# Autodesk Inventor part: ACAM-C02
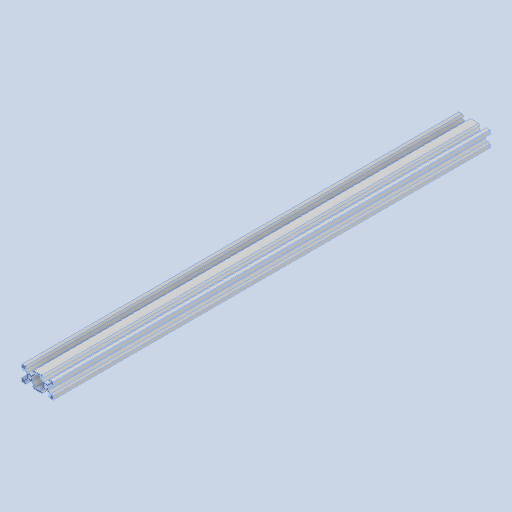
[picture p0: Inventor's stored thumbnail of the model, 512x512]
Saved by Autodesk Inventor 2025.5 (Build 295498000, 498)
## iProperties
Created: 2019-07
Part Number: ACAM-C02
Material: SOLIDWORKS Materials|6063-T5
Document SubType Name: Modeling
Designer: Luis M
Density: 2.7 g/cm^3
Appearance: blue anodized aluminum
Description: Perfil V-Slot 2040 × 550
Sending System: SolidWorks 2018
Last Author: Danish
Last Saved: 2020-09-29
Material_BOM: Aluminio
Proceso_BOM: Comercial
Author: Luis M
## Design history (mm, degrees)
fillet "Fillet1"
sketch "Boceto1"
  geometry: L1 (-15.1, 4.9)-(-15.1, 0.5) reference; L2 (-14.6, 0)-(-10.2, 0) reference; L3 (-10.2, 0)-(-8.2, 2) reference; L4 (-8.2, 2)-(-10.6, 2) reference; L5 (-10.6, 2)-(-10.6, 3.439) reference; L6 (-10.6, 3.439)-(-7.639, 6.4) reference; L7 (-7.639, 6.4)-(-2.561, 6.4) reference; L8 (-2.561, 6.4)-(0.4, 3.439) reference; L9 (0.4, 3.439)-(0.4, 2) reference; L10 (0.4, 2)-(-2, 2) reference; L11 (-2, 2)-(0, 0) reference; L12 (0, 0)-(10.214, 0) reference; L13 (10.214, 0)-(12.214, 2) reference; L14 (12.214, 2)-(9.4, 2) reference; L15 (9.4, 2)-(9.4, 3.439) reference; L16 (9.4, 3.439)-(12.361, 6.4) reference; L17 (12.361, 6.4)-(17.439, 6.4) reference; L18 (17.439, 6.4)-(20.4, 3.439) reference; L19 (20.4, 3.439)-(20.4, 2) reference; L20 (20.4, 2)-(18.414, 2) reference; L21 (18.414, 2)-(20, 0) reference; L22 (20, 0)-(24.4, 0) reference; L23 (24.9, 0.5)-(24.9, 4.9) reference; L24 (24.9, 4.9)-(22.9, 6.9) reference; L25 (22.9, 6.9)-(22.9, 4.5) reference; L26 (22.9, 4.5)-(21.461, 4.5) reference; L27 (21.461, 4.5)-(18.5, 7.461) reference; L28 (18.5, 7.461)-(18.5, 12.539) reference; L29 (18.5, 12.539)-(21.461, 15.5) reference; L30 (21.461, 15.5)-(22.9, 15.5) reference; L31 (22.9, 15.5)-(22.9, 13.1) reference; L32 (22.9, 13.1)-(24.9, 15.1) reference; L33 (24.9, 15.1)-(24.9, 19.5) reference; L34 (24.4, 20)-(20, 20) reference; L35 (20, 20)-(18, 18) reference; L36 (18, 18)-(20.4, 18) reference; L37 (20.4, 18)-(20.4, 16.561) reference; L38 (20.4, 16.561)-(17.439, 13.6) reference; L39 (17.439, 13.6)-(12.361, 13.6) reference; L40 (12.361, 13.6)-(9.4, 16.561) reference; L41 (9.4, 16.561)-(9.4, 18) reference; L42 (9.4, 18)-(12.214, 18) reference; L43 (12.214, 18)-(10.214, 20) reference; L44 (10.214, 20)-(0, 20) reference; L45 (0, 20)-(-2, 18) reference; L46 (-2, 18)-(0.4, 18) reference; L47 (0.4, 18)-(0.4, 16.561) reference; L48 (0.4, 16.561)-(-2.561, 13.6) reference; L49 (-2.561, 13.6)-(-7.639, 13.6) reference; L50 (-7.639, 13.6)-(-10.6, 16.561) reference; L51 (-10.6, 16.561)-(-10.6, 18) reference; L52 (-10.6, 18)-(-8.2, 18) reference; L53 (-8.2, 18)-(-10.2, 20) reference; L54 (-10.2, 20)-(-14.6, 20) reference; L55 (-15.1, 19.5)-(-15.1, 15.1) reference; L56 (-15.1, 15.1)-(-13.1, 13.1) reference; L57 (-13.1, 13.1)-(-13.1, 15.5) reference; L58 (-13.1, 15.5)-(-11.661, 15.5) reference; L59 (-11.661, 15.5)-(-8.7, 12.539) reference; L60 (-8.7, 12.539)-(-8.7, 7.461) reference; L61 (-8.7, 7.461)-(-11.661, 4.5) reference; L62 (-11.661, 4.5)-(-13.1, 4.5) reference; L63 (-13.1, 4.5)-(-13.1, 6.9) reference; L64 (-13.1, 6.9)-(-15.1, 4.9) reference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; C1 r 2.1 at (-5.1, 10) reference; C2 r 2.1 at (14.9, 10) reference; A1 r 0.5 centre (-14.6, 0.5) between (-15.1, 0.5) and (-14.6, 0) reference; A2 r 0.5 centre (24.4, 0.5) between (24.4, 0) and (24.9, 0.5) reference; A3 r 0.5 centre (24.4, 19.5) between (24.9, 19.5) and (24.4, 20) reference; A4 r 0.5 centre (-14.6, 19.5) between (-14.6, 20) and (-15.1, 19.5) reference; 1 further point
extrude "Extrusión1" join sketch "Boceto1" distance "d0" = 150; taper "d1" = 0 deg
node "Sólido1"
node "Contorno proyectado1"
